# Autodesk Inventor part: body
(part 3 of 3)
sketch "Sketch150"
  geometry: L1 (-115, 140.221)-(-115, 134.332) reference; L2 (-115, 134.332)-(-122.377, 134.332) reference; L3 (-122.377, 134.332)-(-122.377, 140.221) reference; L4 (-122.377, 140.221)-(-115, 140.221) reference; L5 (-131, 141.166)-(-131, 148) reference; L6 (-131, 148)-(-123.589, 148) reference; L7 (-123.589, 148)-(-123.589, 141.166) reference; L8 (-123.589, 141.166)-(-131, 141.166) reference; L9 (-115, 141.166)-(-122.377, 141.166) reference; L10 (-122.377, 141.166)-(-122.377, 148) reference; L11 (-122.377, 148)-(-115, 148) reference; L12 (-115, 148)-(-115, 141.166) reference; L13 (-131, 140.221)-(-123.589, 140.221) reference; L14 (-123.589, 140.221)-(-123.589, 134.332) reference; L15 (-123.589, 134.332)-(-131, 134.332) reference; L16 (-131, 134.332)-(-131, 140.221) reference; L17 (-113.739, 149.568)-(-132.264, 149.568); L18 (-132.264, 149.568)-(-132.264, 132.978); L19 (-132.264, 132.978)-(-113.739, 132.978); L20 (-113.739, 132.978)-(-113.739, 149.568); 1 further point
  constraints: 8 end point, 2 parallel, 1 horizontal, 1 perpendicular
extrude "Extrusion150" cut sketch "Sketch150" distance "d349" = 1.25; taper "d350" = 0 deg
sketch "Sketch151"
  geometry: L1 (126.488, 149.508)-(126.488, 118) reference; L2 (126.488, 118)-(100, 118) reference; L3 (100, 118)-(100, 149.508) reference; L4 (100, 149.508)-(126.488, 149.508) reference; L5 (125.254, 134.332)-(101.544, 134.332); L6 (101.544, 134.332)-(101.544, 148.025); L7 (101.544, 148.025)-(125.254, 148.025); L8 (125.254, 148.025)-(125.254, 134.332); L9 (125.254, 132.001)-(101.544, 132.001); L10 (101.544, 132.001)-(101.544, 118.95); L11 (101.544, 118.95)-(125.254, 118.95); L12 (125.254, 118.95)-(125.254, 132.001); 1 further point
  constraints: 16 end point, 4 parallel, 2 horizontal, 2 perpendicular
extrude "Extrusion151" join sketch "Sketch151" distance "d351" = 1.25; taper "d352" = 0 deg
sketch "Sketch152"
  geometry: L1 (-125.254, 134.332)-(-125.254, 148.025) reference; L2 (-125.254, 148.025)-(-101.544, 148.025) reference; L3 (-101.544, 148.025)-(-101.544, 134.332) reference; L4 (-101.544, 134.332)-(-125.254, 134.332) reference; L5 (-126.488, 118)-(-126.488, 149.508) reference; L6 (-100, 149.508)-(-100, 118) reference; L7 (-126.488, 149.508)-(-100, 149.508) reference; L8 (-126.488, 132.993)-(-100, 132.993); 1 further point
  constraints: 2 end point, 2 point on line, 1 parallel
extrude "Extrusion152" join sketch "Sketch152" distance "d353" = 1.25; taper "d354" = 0 deg
sketch "Sketch153"
  geometry: L1 (101.544, 118.95)-(101.544, 132.001) reference; L2 (125.254, 132.001)-(125.254, 118.95) reference; L3 (125.254, 118.95)-(101.544, 118.95) reference; L4 (125.254, 148.025)-(125.254, 134.332) reference; L5 (101.544, 134.332)-(101.544, 148.025) reference; L6 (101.544, 148.025)-(125.254, 148.025) reference; L7 (125.254, 141.178)-(101.544, 141.178); L8 (101.544, 141.178)-(101.544, 140.119); L9 (101.544, 140.119)-(125.254, 140.119); L10 (125.254, 140.119)-(125.254, 141.178); L11 (125.254, 126.04)-(101.544, 126.04); L12 (101.544, 126.04)-(101.544, 124.925); L13 (101.544, 124.925)-(125.254, 124.925); L14 (125.254, 124.925)-(125.254, 126.04); L15 (108.73, 148.025)-(109.845, 148.025); L16 (109.845, 148.025)-(109.845, 118.95); L17 (109.845, 118.95)-(108.73, 118.95); L18 (108.73, 118.95)-(108.73, 148.025); L19 (117.478, 148.025)-(118.766, 148.025); L20 (118.766, 148.025)-(118.766, 118.95); L21 (118.766, 118.95)-(117.478, 118.95); L22 (117.478, 118.95)-(117.478, 148.025); 1 further point
  constraints: 32 end point, 8 parallel, 7 point on line, 4 horizontal, 4 perpendicular, 1 midpoint
extrude "Extrusion153" join sketch "Sketch153" distance "d355" = 0.75; taper "d356" = 0 deg
sketch "Sketch154"
  geometry: L1 (-117.478, 134.332)-(-118.766, 134.332) reference; L2 (-117.478, 134.332)-(-117.478, 140.119) reference; L3 (-117.478, 140.119)-(-109.845, 140.119) reference; L4 (-109.845, 140.119)-(-109.845, 134.332) reference; L5 (-108.73, 134.332)-(-109.845, 134.332) reference; L6 (-108.73, 134.332)-(-108.73, 140.119) reference; L7 (-108.73, 140.119)-(-101.544, 140.119) reference; L8 (-101.544, 141.178)-(-101.544, 140.119) reference; L9 (-101.544, 141.178)-(-108.73, 141.178) reference; L10 (-108.73, 141.178)-(-108.73, 148.025) reference; L11 (-109.845, 148.025)-(-108.73, 148.025) reference; L12 (-109.845, 148.025)-(-109.845, 141.178) reference; L13 (-109.845, 141.178)-(-117.478, 141.178) reference; L14 (-117.478, 141.178)-(-117.478, 148.025) reference; L15 (-118.766, 148.025)-(-117.478, 148.025) reference; L16 (-118.766, 148.025)-(-118.766, 141.178) reference; L17 (-118.766, 141.178)-(-125.254, 141.178) reference; L18 (-125.254, 140.119)-(-125.254, 141.178) reference; L19 (-125.254, 140.119)-(-118.766, 140.119) reference; L20 (-118.766, 140.119)-(-118.766, 134.332) reference; 1 further point
extrude "Extrusion154" join sketch "Sketch154" distance "d357" = 0.75; taper "d358" = 0 deg
sketch "Sketch155"
  geometry: L1 (117.478, 134.332)-(109.845, 134.332) reference; L2 (109.845, 134.332)-(109.845, 140.119) reference; L3 (109.845, 140.119)-(117.478, 140.119) reference; L4 (117.478, 140.119)-(117.478, 134.332) reference; L5 (108.73, 134.332)-(101.544, 134.332) reference; L6 (101.544, 134.332)-(101.544, 140.119) reference; L7 (101.544, 140.119)-(108.73, 140.119) reference; L8 (108.73, 140.119)-(108.73, 134.332) reference; L9 (118.766, 134.332)-(118.766, 140.119) reference; L10 (118.766, 140.119)-(125.254, 140.119) reference; L11 (125.254, 140.119)-(125.254, 134.332) reference; L12 (125.254, 134.332)-(118.766, 134.332) reference; L13 (101.544, 141.178)-(101.544, 148.025) reference; L14 (101.544, 148.025)-(108.73, 148.025) reference; L15 (108.73, 148.025)-(108.73, 141.178) reference; L16 (108.73, 141.178)-(101.544, 141.178) reference; L17 (109.845, 148.025)-(117.478, 148.025) reference; L18 (117.478, 148.025)-(117.478, 141.178) reference; L19 (117.478, 141.178)-(109.845, 141.178) reference; L20 (109.845, 141.178)-(109.845, 148.025) reference; L21 (125.254, 141.178)-(118.766, 141.178) reference; L22 (118.766, 141.178)-(118.766, 148.025) reference; L23 (118.766, 148.025)-(125.254, 148.025) reference; L24 (125.254, 148.025)-(125.254, 141.178) reference; L25 (99.825, 132.904)-(126.573, 132.904); L26 (126.573, 132.904)-(126.573, 149.564); L27 (126.573, 149.564)-(99.825, 149.564); L28 (99.825, 149.564)-(99.825, 132.904); 1 further point
  constraints: 8 end point, 2 parallel, 1 horizontal, 1 perpendicular
extrude "Extrusion155" cut sketch "Sketch155" distance "d359" = 0.75; taper "d360" = 0 deg
sketch "Sketch156"
  geometry: L1 (-132.114, -65.343)-(-128.305, -65.343); L2 (-128.305, -65.343)-(-128.305, -73.595); L3 (-128.305, -73.595)-(-132.114, -73.595); L4 (-132.114, -73.595)-(-132.114, -65.343); 1 further point
  constraints: 8 end point, 2 parallel, 1 horizontal, 1 perpendicular
extrude "Extrusion156" join sketch "Sketch156" distance "d361" = 6; taper "d363" = 0 deg; dims "d362" = 135.125, "d364" = 0
chamfer "Chamfer10" distance "d365" = 2; stored, may be unused: second distance "d366" = 2, angle "d367" = 45 deg
chamfer "Chamfer11" distance "d368" = 2.99; stored, may be unused: second distance "d369" = 2, angle "d370" = 45 deg
chamfer "Chamfer12" distance "d371" = 6.6; stored, may be unused: second distance "d372" = 2, angle "d373" = 45 deg
chamfer "Chamfer13" distance "d374" = 6.49; stored, may be unused: second distance "d375" = 2, angle "d376" = 45 deg
chamfer "Chamfer14" distance "d377" = 6.49; stored, may be unused: second distance "d378" = 2, angle "d379" = 45 deg
sketch "Sketch157"
  geometry: L1 (86, -22.522)-(104, -22.522) reference; L2 (104, -55)-(86, -55) reference; L3 (26, -55)-(8, -55) reference; L4 (8, -22.522)-(26, -22.522) reference; L5 (26, -22.522)-(26, -55) reference; L6 (17, -22.522)-(16, -22.522); L7 (16, -22.522)-(16, -55); L8 (16, -55)-(17, -55); L9 (17, -55)-(17, -22.522); L10 (17, -55)-(18, -55); L11 (18, -55)-(18, -22.522); L12 (18, -22.522)-(17, -22.522); L13 (17, -22.522)-(17, -55); L14 (95, -22.522)-(94, -22.522); L15 (94, -22.522)-(94, -55); L16 (94, -55)-(95, -55); L17 (95, -55)-(95, -22.522); L18 (95, -55)-(96, -55); L19 (96, -55)-(96, -22.522); L20 (96, -22.522)-(95, -22.522); L21 (95, -22.522)-(95, -55); L22 (104.519, -39.261)-(85.481, -39.261); L23 (85.481, -39.261)-(85.481, -38.261); L24 (85.481, -38.261)-(104.519, -38.261); L25 (104.519, -38.261)-(104.519, -39.261); L26 (104.519, -39.261)-(85.481, -38.261); L27 (85.481, -39.261)-(104.519, -38.261); L28 (8, -39.761)-(26, -39.761); L29 (26, -39.761)-(26, -38.761); L30 (26, -38.761)-(8, -38.761); L31 (8, -38.761)-(8, -39.761); L32 (8, -39.761)-(26, -38.761); L33 (26, -39.761)-(8, -38.761); 3 further points
  constraints: 56 end point, 12 parallel, 8 midpoint, 6 horizontal, 6 perpendicular, 5 point on line
  dimensions: "d380" = 1 distance of L8.end L7.end; "d381" = 1 distance of L12.end L11.end; "d382" = 1 distance of L16.end L15.end; "d383" = 1 distance of L20.end L19.end; "d384" = 1 distance of L22.end L23.end
extrude "Extrusion157" join sketch "Sketch157" distance "d385" = 2; taper "d386" = 0 deg
sketch "Sketch158"
  geometry: L1 (104.795, -31.141)-(85.205, -31.141); L2 (85.205, -31.141)-(85.205, -30.141); L3 (85.205, -30.141)-(104.795, -30.141); L4 (104.795, -30.141)-(104.795, -31.141); L5 (104.795, -31.141)-(85.205, -30.141); L6 (85.205, -31.141)-(104.795, -30.141); L7 (105.662, -47.88)-(84.338, -47.88); L8 (84.338, -47.88)-(84.338, -46.88); L9 (84.338, -46.88)-(105.662, -46.88); L10 (105.662, -46.88)-(105.662, -47.88); L11 (105.662, -47.88)-(84.338, -46.88); L12 (84.338, -47.88)-(105.662, -46.88); L13 (6.154, -30.141)-(27.846, -30.141); L14 (27.846, -30.141)-(27.846, -31.141); L15 (27.846, -31.141)-(6.154, -31.141); L16 (6.154, -31.141)-(6.154, -30.141); L17 (6.154, -30.141)-(27.846, -31.141); L18 (27.846, -30.141)-(6.154, -31.141); L19 (6.926, -46.88)-(27.074, -46.88); L20 (27.074, -46.88)-(27.074, -47.88); L21 (27.074, -47.88)-(6.926, -47.88); L22 (6.926, -47.88)-(6.926, -46.88); L23 (6.926, -46.88)-(27.074, -47.88); L24 (27.074, -46.88)-(6.926, -47.88); 5 further points
  constraints: 48 end point, 8 midpoint, 8 parallel, 4 horizontal, 4 perpendicular
  dimensions: "d387" = 1 distance of L1.end L2.end; "d388" = 1 distance of L7.end L8.end
extrude "Extrusion158" join sketch "Sketch158" distance "d389" = 2; taper "d390" = 0 deg
sketch "Sketch159"
  geometry: L1 (14, -178)-(126, -178) reference; L2 (31.976, -34.46)-(20.875, -34.46) reference; L3 (120.832, -178)-(115.933, -182.888); L4 (115.933, -182.888)-(24.079, -182.888); L5 (24.079, -182.888)-(19.202, -178); 1 further point
  constraints: 6 end point, 2 point on line, 1 parallel, 1 perpendicular
extrude "Extrusion159" join sketch "Sketch159" distance "d391" = 4.00022; taper "d392" = 0 deg
sketch "Sketch160"
  geometry: L1 (78, -15)-(34, -15); L2 (34, -15)-(34, -124); L3 (34, -124)-(78, -124); L4 (78, -124)-(78, -15); 1 further point
  constraints: 8 end point, 2 parallel, 1 horizontal, 1 perpendicular
extrude "Extrusion160" join sketch "Sketch160" distance "d393" = 4; taper "d394" = 0 deg
fillet "Fillet4" dims "d395" = 10
chamfer "Chamfer15" distance "d396" = 4; stored, may be unused: second distance "d397" = 2, angle "d398" = 45 deg
sketch "Sketch161"
  geometry: L1 (74, -47.663)-(74, -114) reference; L2 (56, -56)-(56, -32); L3 (53, -56)-(53, -32); L4 (59, -32)-(59, -56); L5 (56, -107)-(56, -83); L6 (53, -107)-(53, -83); L7 (59, -83)-(59, -107); C1 r 7 at (56, -107); C2 r 7 at (56, -56); A1 r 3 centre (56, -56) between (53, -56) and (59, -56); A2 r 3 centre (56, -32) between (59, -32) and (53, -32); A3 r 3 centre (56, -107) between (53, -107) and (59, -107); A4 r 3 centre (56, -83) between (59, -83) and (53, -83); 3 further points
  constraints: 16 end point, 8 point on circle, 8 tangent, 6 centre point, 4 parallel, 2 midpoint
extrude "Extrusion161" cut sketch "Sketch161" distance "d399" = 10.75; taper "d400" = 0 deg
sketch "Sketch162"
  geometry: L1 (53, -49.675)-(53, -32) reference; L2 (59, -32)-(59, -49.675) reference; L3 (53, -100.675)-(53, -83) reference; L4 (59, -83)-(59, -100.675) reference; L5 (38, -114)-(38, -47.663) reference; L6 (56, -107)-(56, -83); L7 (49, -107)-(49, -83); L8 (63, -83)-(63, -107); L9 (56, -56)-(56, -32); L10 (49, -56)-(49, -32); L11 (63, -32)-(63, -56); A1 r 3 centre (56, -32) between (59, -32) and (53, -32) reference; A2 r 7 centre (56, -56) between (53, -49.675) and (59, -49.675) reference; A3 r 3 centre (56, -83) between (59, -83) and (53, -83) reference; A4 r 7 centre (56, -107) between (53, -100.675) and (59, -100.675) reference; A5 r 7 centre (56, -107) between (49, -107) and (63, -107); A6 r 7 centre (56, -83) between (63, -83) and (49, -83); A7 r 7 centre (56, -56) between (49, -56) and (63, -56); A8 r 7 centre (56, -32) between (63, -32) and (49, -32); 3 further points
  constraints: 16 end point, 8 point on circle, 8 tangent, 4 centre point, 4 parallel, 2 midpoint
extrude "Extrusion162" cut sketch "Sketch162" distance "d401" = 4; taper "d402" = 0 deg
chamfer "Chamfer16" distance "d403" = 3; stored, may be unused: second distance "d404" = 2, angle "d405" = 45 deg
fillet "Fillet5" dims "d406" = 6
sketch "Sketch163"
  geometry: L1 (0, 0)-(0, 86) reference; L2 (112, 0)-(0, 0); L3 (0, 0)-(0, 5); L4 (0, 5)-(112, 5); L5 (112, 5)-(112, 0); 1 further point
  constraints: 8 end point, 2 parallel, 1 horizontal, 1 perpendicular, 1 point on line
extrude "Extrusion163" join sketch "Sketch163" distance "d407" = 6; taper "d408" = 0 deg
chamfer "Chamfer17" distance "d409" = 6; stored, may be unused: second distance "d410" = 2, angle "d411" = 45 deg
sketch "Sketch164"
  geometry: L1 (112, -66.522)-(107, -66.522); L2 (107, -66.522)-(107, -62); L3 (107, -62)-(112, -62); L4 (112, -62)-(112, -66.522); L5 (0, -66.522)-(5, -66.522); L6 (5, -66.522)-(5, -62); L7 (5, -62)-(0, -62); L8 (0, -62)-(0, -66.522); 1 further point
  constraints: 16 end point, 4 parallel, 2 horizontal, 2 perpendicular
extrude "Extrusion164" join sketch "Sketch164" distance "d412" = 87; taper "d413" = 0 deg
chamfer "Chamfer18" distance "d414" = 5; stored, may be unused: second distance "d415" = 2, angle "d416" = 45 deg
sketch "Sketch165"
  geometry: L1 (14, -200)-(14, -178) reference; L2 (115.933, -182.888)-(120.832, -178) reference; L3 (126, -178)-(126, -200) reference; L4 (31.976, -34.46)-(20.875, -34.46) reference; L5 (14, -196.844)-(18.833, -196.844); L6 (18.833, -196.844)-(18.833, -186.125); L7 (18.833, -186.125)-(14, -181.281); L8 (126, -196.844)-(121.146, -196.844); L9 (121.146, -196.844)-(121.146, -186.125); L10 (121.146, -186.125)-(126, -181.282); 1 further point
  constraints: 12 end point, 5 perpendicular, 4 point on line, 1 parallel
extrude "Extrusion165" join sketch "Sketch165" distance "d417" = 90.22222; taper "d418" = 0 deg
chamfer "Chamfer19" distance "d419" = 4.75; stored, may be unused: second distance "d420" = 2, angle "d421" = 45 deg
chamfer "Chamfer20" distance "d422" = 1; stored, may be unused: second distance "d423" = 2, angle "d424" = 45 deg
chamfer "Chamfer21" distance "d425" = 0.5; stored, may be unused: second distance "d426" = 2, angle "d427" = 45 deg
chamfer "Chamfer22" distance "d428" = 0.5; stored, may be unused: second distance "d429" = 2, angle "d430" = 45 deg
chamfer "Chamfer23" distance "d431" = 0.5; stored, may be unused: second distance "d432" = 2, angle "d433" = 45 deg
chamfer "Chamfer24" distance "d434" = 0.5; stored, may be unused: second distance "d435" = 2, angle "d436" = 45 deg
chamfer "Chamfer25" distance "d437" = 0.5; stored, may be unused: second distance "d438" = 2, angle "d439" = 45 deg
chamfer "Chamfer26" distance "d440" = 0.5; stored, may be unused: second distance "d441" = 2, angle "d442" = 45 deg
chamfer "Chamfer27" distance "d443" = 2; stored, may be unused: second distance "d444" = 0.5, angle "d445" = 45 deg
chamfer "Chamfer28" distance "d446" = 2; stored, may be unused: second distance "d447" = 0.5, angle "d448" = 45 deg
chamfer "Chamfer29" distance "d449" = 2; stored, may be unused: second distance "d450" = 0.5, angle "d451" = 45 deg
chamfer "Chamfer30" distance "d452" = 2; stored, may be unused: second distance "d453" = 0.5, angle "d454" = 45 deg
chamfer "Chamfer31" distance "d455" = 1.5; stored, may be unused: second distance "d456" = 0.5, angle "d457" = 45 deg
chamfer "Chamfer32" distance "d458" = 2; stored, may be unused: second distance "d459" = 0.5, angle "d460" = 45 deg
chamfer "Chamfer33" distance "d461" = 2; stored, may be unused: second distance "d462" = 0.5, angle "d463" = 45 deg
chamfer "Chamfer34" distance "d464" = 2; stored, may be unused: second distance "d465" = 0.5, angle "d466" = 45 deg
chamfer "Chamfer35" distance "d467" = 2; stored, may be unused: second distance "d468" = 0.5, angle "d469" = 45 deg
chamfer "Chamfer36" distance "d470" = 2; stored, may be unused: second distance "d471" = 0.5, angle "d472" = 45 deg
chamfer "Chamfer37" distance "d473" = 2; stored, may be unused: second distance "d474" = 0.5, angle "d475" = 45 deg
chamfer "Chamfer38" distance "d476" = 2; stored, may be unused: second distance "d477" = 0.5, angle "d478" = 45 deg
chamfer "Chamfer39" distance "d479" = 2; stored, may be unused: second distance "d480" = 0.5, angle "d481" = 45 deg
chamfer "Chamfer40" distance "d482" = 2; stored, may be unused: second distance "d483" = 0.5, angle "d484" = 45 deg
chamfer "Chamfer41" distance "d485" = 2; stored, may be unused: second distance "d486" = 0.5, angle "d487" = 45 deg
chamfer "Chamfer42" distance "d488" = 2; stored, may be unused: second distance "d489" = 0.5, angle "d490" = 45 deg
chamfer "Chamfer43" distance "d491" = 2; stored, may be unused: second distance "d492" = 0.5, angle "d493" = 45 deg
chamfer "Chamfer44" distance "d494" = 1.75; stored, may be unused: second distance "d495" = 0.5, angle "d496" = 45 deg
chamfer "Chamfer45" distance "d497" = 2; stored, may be unused: second distance "d498" = 0.5, angle "d499" = 45 deg
chamfer "Chamfer46" distance "d500" = 2; stored, may be unused: second distance "d501" = 0.5, angle "d502" = 45 deg
chamfer "Chamfer47" distance "d503" = 2; stored, may be unused: second distance "d504" = 0.5, angle "d505" = 45 deg
chamfer "Chamfer48" distance "d506" = 2; stored, may be unused: second distance "d507" = 0.5, angle "d508" = 45 deg
chamfer "Chamfer49" distance "d509" = 2; stored, may be unused: second distance "d510" = 0.5, angle "d511" = 45 deg
chamfer "Chamfer50" distance "d512" = 2; stored, may be unused: second distance "d513" = 0.5, angle "d514" = 45 deg
chamfer "Chamfer51" distance "d515" = 2; stored, may be unused: second distance "d516" = 0.5, angle "d517" = 45 deg
chamfer "Chamfer52" distance "d518" = 2; stored, may be unused: second distance "d519" = 0.5, angle "d520" = 45 deg
chamfer "Chamfer53" distance "d521" = 2; stored, may be unused: second distance "d522" = 0.5, angle "d523" = 45 deg
chamfer "Chamfer54" distance "d524" = 2; stored, may be unused: second distance "d525" = 0.5, angle "d526" = 45 deg
chamfer "Chamfer55" distance "d527" = 2; stored, may be unused: second distance "d528" = 0.5, angle "d529" = 45 deg
chamfer "Chamfer56" distance "d530" = 2; stored, may be unused: second distance "d531" = 0.5, angle "d532" = 45 deg
chamfer "Chamfer57" distance "d533" = 2; stored, may be unused: second distance "d534" = 0.5, angle "d535" = 45 deg
chamfer "Chamfer58" distance "d536" = 2; stored, may be unused: second distance "d537" = 0.5, angle "d538" = 45 deg
chamfer "Chamfer59" distance "d539" = 2; stored, may be unused: second distance "d540" = 0.5, angle "d541" = 45 deg
chamfer "Chamfer60" distance "d542" = 2; stored, may be unused: second distance "d543" = 0.5, angle "d544" = 45 deg
chamfer "Chamfer61" distance "d545" = 2; stored, may be unused: second distance "d546" = 0.5, angle "d547" = 45 deg
chamfer "Chamfer62" distance "d548" = 2; stored, may be unused: second distance "d549" = 0.5, angle "d550" = 45 deg
chamfer "Chamfer63" distance "d551" = 2; stored, may be unused: second distance "d552" = 0.5, angle "d553" = 45 deg
chamfer "Chamfer64" distance "d554" = 2; stored, may be unused: second distance "d555" = 0.5, angle "d556" = 45 deg
chamfer "Chamfer65" distance "d557" = 2; stored, may be unused: second distance "d558" = 0.5, angle "d559" = 45 deg
chamfer "Chamfer66" distance "d560" = 2; stored, may be unused: second distance "d561" = 0.5, angle "d562" = 45 deg
chamfer "Chamfer67" distance "d563" = 2; stored, may be unused: second distance "d564" = 0.5, angle "d565" = 45 deg
chamfer "Chamfer68" distance "d566" = 2; stored, may be unused: second distance "d567" = 0.5, angle "d568" = 45 deg
chamfer "Chamfer69" distance "d569" = 2; stored, may be unused: second distance "d570" = 0.5, angle "d571" = 45 deg
chamfer "Chamfer70" distance "d572" = 2; stored, may be unused: second distance "d573" = 0.5, angle "d574" = 45 deg
chamfer "Chamfer71" distance "d575" = 2; stored, may be unused: second distance "d576" = 0.5, angle "d577" = 45 deg
chamfer "Chamfer72" distance "d578" = 2; stored, may be unused: second distance "d579" = 0.5, angle "d580" = 45 deg
chamfer "Chamfer73" distance "d581" = 2; stored, may be unused: second distance "d582" = 0.5, angle "d583" = 45 deg
chamfer "Chamfer74" distance "d584" = 2; stored, may be unused: second distance "d585" = 0.5, angle "d586" = 45 deg
chamfer "Chamfer75" distance "d587" = 2; stored, may be unused: second distance "d588" = 0.5, angle "d589" = 45 deg
chamfer "Chamfer76" distance "d590" = 2; stored, may be unused: second distance "d591" = 0.5, angle "d592" = 45 deg
chamfer "Chamfer77" distance "d593" = 2; stored, may be unused: second distance "d594" = 0.5, angle "d595" = 45 deg
chamfer "Chamfer78" distance "d596" = 2; stored, may be unused: second distance "d597" = 0.5, angle "d598" = 45 deg
chamfer "Chamfer79" distance "d599" = 2; stored, may be unused: second distance "d600" = 0.5, angle "d601" = 45 deg
chamfer "Chamfer80" distance "d602" = 1.25; stored, may be unused: second distance "d603" = 0.5, angle "d604" = 45 deg
chamfer "Chamfer81" distance "d605" = 1.25; stored, may be unused: second distance "d606" = 0.5, angle "d607" = 45 deg
chamfer "Chamfer82" distance "d608" = 1.25; stored, may be unused: second distance "d609" = 0.5, angle "d610" = 45 deg
chamfer "Chamfer83" distance "d611" = 2; stored, may be unused: second distance "d612" = 0.5, angle "d613" = 45 deg
chamfer "Chamfer84" distance "d614" = 2; stored, may be unused: second distance "d615" = 0.5, angle "d616" = 45 deg
chamfer "Chamfer85" distance "d617" = 2; stored, may be unused: second distance "d618" = 0.5, angle "d619" = 45 deg
chamfer "Chamfer86" distance "d620" = 2; stored, may be unused: second distance "d621" = 0.5, angle "d622" = 45 deg
chamfer "Chamfer87" distance "d623" = 2; stored, may be unused: second distance "d624" = 0.5, angle "d625" = 45 deg
chamfer "Chamfer88" distance "d626" = 2; stored, may be unused: second distance "d627" = 0.5, angle "d628" = 45 deg
chamfer "Chamfer89" distance "d629" = 2; stored, may be unused: second distance "d630" = 0.5, angle "d631" = 45 deg
chamfer "Chamfer90" distance "d632" = 2; stored, may be unused: second distance "d633" = 0.5, angle "d634" = 45 deg
chamfer "Chamfer91" distance "d635" = 2; stored, may be unused: second distance "d636" = 0.5, angle "d637" = 45 deg
chamfer "Chamfer92" distance "d638" = 2; stored, may be unused: second distance "d639" = 0.5, angle "d640" = 45 deg
chamfer "Chamfer93" distance "d641" = 2; stored, may be unused: second distance "d642" = 0.5, angle "d643" = 45 deg
chamfer "Chamfer94" distance "d644" = 2; stored, may be unused: second distance "d645" = 0.5, angle "d646" = 45 deg
chamfer "Chamfer95" distance "d647" = 0.5; stored, may be unused: second distance "d648" = 0.5, angle "d649" = 45 deg
sketch "Sketch166"
  geometry: L1 (-9.13, -36.87)-(0.44, -36.87); L2 (0.44, -36.87)-(0.44, -53.44); L3 (0.44, -53.44)-(-9.13, -53.44); L4 (-9.13, -53.44)-(-9.13, -36.87); 1 further point
  constraints: 8 end point, 2 parallel, 1 horizontal, 1 perpendicular
extrude "Extrusion166" cut sketch "Sketch166" distance "d650" = 18.77778; taper "d651" = 0 deg
chamfer "Chamfer96" distance "d652" = 3.5; stored, may be unused: second distance "d653" = 0.5, angle "d654" = 45 deg
chamfer "Chamfer97" distance "d655" = 2; stored, may be unused: second distance "d656" = 0.5, angle "d657" = 45 deg
sketch "Sketch167"
  geometry: L1 (4, -55)-(4, -35) reference; L2 (2, -33)-(-11, -33) reference; L3 (-13, -35)-(-13, -55) reference; L4 (-4.5, -33)-(-6, -33); L5 (-6, -33)-(-6, -35); L6 (-6, -35)-(-4.5, -35); L7 (-4.5, -35)-(-4.5, -33); L8 (-4.5, -35)-(-3, -35); L9 (-3, -35)-(-3, -33); L10 (-3, -33)-(-4.5, -33); L11 (-4.5, -33)-(-4.5, -35); L12 (4, -45)-(2.5, -45); L13 (2.5, -45)-(2.5, -43); L14 (2.5, -43)-(4, -43); L15 (4, -43)-(4, -45); L16 (4, -45)-(2.5, -45); L17 (2.5, -45)-(2.5, -47); L18 (2.5, -47)-(4, -47); L19 (4, -47)-(4, -45); L20 (-13, -43)-(-11.5, -43); L21 (-11.5, -43)-(-11.5, -47); L22 (-11.5, -47)-(-13, -47); L23 (-13, -47)-(-13, -43); 1 further point
  constraints: 40 end point, 10 parallel, 5 horizontal, 5 perpendicular, 2 midpoint, 2 point on line
  dimensions: "d658" = 1.5 distance of L13.end L14.end; "d659" = 1.5 distance of L21.end L22.end
extrude "Extrusion167" join sketch "Sketch167" distance "d660" = 13.02778; taper "d661" = 0 deg
chamfer "Chamfer98" distance "d662" = 1.5; stored, may be unused: second distance "d663" = 0.5, angle "d664" = 45 deg
chamfer "Chamfer99" distance "d665" = 1.5; stored, may be unused: second distance "d666" = 0.5, angle "d667" = 45 deg
sketch "Sketch168"
  geometry: L1 (-1.712, 154.276)-(2.594, 154.276); L2 (2.594, 154.276)-(2.594, 150.276); L3 (2.594, 150.276)-(-4.582, 150.276); L4 (2.594, 149)-(2.594, 145); L5 (2.594, 145)-(-6.406, 145); L6 (-6.406, 145)-(-6.406, 147.734); L7 (-5.497, 149)-(2.594, 149); L8 (-7.671, 145.97)-(-7.671, 145); L9 (-7.671, 145)-(-8.367, 145); L10 (6, 144)-(6, 140); L11 (6, 140)-(-3, 140); L12 (-3, 140)-(-3, 144); L13 (-3, 144)-(6, 144); L14 (-4, 144)-(-4, 140); L15 (-4, 140)-(-11.954, 140); L16 (-9.084, 144)-(-4, 144); L17 (1, 139)-(1, 135); L18 (1, 135)-(-8, 135); L19 (-8, 135)-(-8, 139); L20 (-8, 139)-(1, 139); L21 (-9, 139)-(-9, 135); L22 (-9, 135)-(-15.541, 135); L23 (-12.671, 139)-(-9, 139); L24 (6, 134)-(6, 130); L25 (6, 130)-(-3, 130); L26 (-3, 130)-(-3, 134); L27 (-3, 134)-(6, 134); L28 (-4, 134)-(-4, 130); L29 (-4, 130)-(-13, 130); L30 (-13, 130)-(-13, 134); L31 (-13, 134)-(-4, 134); L32 (-14, 134)-(-14, 130); L33 (-14, 130)-(-19.128, 130); L34 (-16.258, 134)-(-14, 134); L35 (-9, 129)-(-9, 125); L36 (-9, 125)-(-18, 125); L37 (-18, 125)-(-18, 129); L38 (-18, 129)-(-9, 129); L39 (1, 129)-(1, 125); L40 (1, 125)-(-8, 125); L41 (-8, 125)-(-8, 129); L42 (-8, 129)-(1, 129); L43 (-19, 129)-(-19, 125); L44 (-19, 125)-(-22, 125); L45 (-19.845, 129)-(-19, 129); L46 (-3, 124)-(6, 124); L47 (6, 120)-(-3, 120); L48 (6, 124)-(6, 120); L49 (-4, 124)-(-4, 120); L50 (-8, 119)-(1, 119); L51 (1, 119)-(1, 115); L52 (1, 115)-(-8, 115); L53 (-8, 115)-(-8, 119); L54 (-3, 120)-(-3, 124); L55 (-13, 124)-(-4, 124); L56 (-4, 120)-(-13, 120); L57 (-13, 120)-(-13, 124); L58 (-18, 119)-(-9, 119); L59 (-9, 115)-(-18, 115); L60 (-9, 119)-(-9, 115); L61 (-18, 115)-(-18, 119); L62 (-19, 119)-(-19, 115); L63 (-14, 120)-(-23, 120); L64 (-23, 120)-(-23, 124)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; 1 further point
  constraints: 716 end point, 172 parallel, 88 horizontal, 88 perpendicular, 2 collinear, 2 point on line
extrude "Extrusion168" cut sketch "Sketch168" distance "d668" = 0.5; taper "d669" = 0 deg
sketch "Sketch169"
  geometry: L1 (0.5, 157)-(0.5, 144) reference; L2 (0.242, 157)-(0.5, 157) reference; L3 (-22, 124)-(-22, 125.957) reference; L4 (0.5, 14)-(-3, 14) reference; L5 (-9.072, 144)-(-4, 144); L6 (-4, 144)-(-4, 140); L7 (-4, 140)-(-11.938, 140); L8 (-9.072, 139)-(-9.072, 135); L9 (-9.072, 135)-(-15.521, 135); L10 (-9.072, 139)-(-12.655, 139); L11 (-14, 134)-(-14, 130); L12 (-14, 130)-(-19.103, 130); L13 (-14, 134)-(-16.237, 134); L14 (-19.82, 129)-(-19.103, 129); L15 (-19.103, 129)-(-19.103, 124.978); L16 (-19.103, 124.978)-(-22, 124.978); L17 (0.5, 145)-(-8.356, 145); L18 (0.5, 149.41)-(-5.196, 149.41); L19 (0.5, 150.5)-(-4.415, 150.5); 1 further point
  constraints: 30 end point, 8 parallel, 6 perpendicular, 2 midpoint, 2 point on line, 11 other
extrude "Extrusion169" join sketch "Sketch169" distance "d670" = 0.5; taper "d671" = 0 deg
sketch "Sketch170"
  geometry: L1 (-1.322, 151.905)-(-1.322, 144.25) reference; L2 (0, 151.905)-(0, 176.929) reference; L3 (-5.936, 162.782)-(-5.936, 173.075) reference; L4 (-6.364, 162)-(-6.364, 155.5) reference; L5 (-7.071, 9)-(0, 9); L6 (0, 9)-(0, 10); L7 (0, 10)-(-7.071, 10); L8 (-7.071, 10)-(-7.071, 9); L9 (-7.071, 14)-(0, 14); L10 (0, 14)-(0, 15); L11 (0, 15)-(-7.071, 15); L12 (-7.071, 15)-(-7.071, 14); L13 (-7.071, 19)-(0, 19); L14 (0, 19)-(0, 20); L15 (0, 20)-(-7.071, 20); L16 (-7.071, 20)-(-7.071, 19); L17 (-7.071, 24)-(0, 24); L18 (0, 24)-(0, 25); L19 (0, 25)-(-7.071, 25); L20 (-7.071, 25)-(-7.071, 24); L21 (-7.071, 29)-(0, 29); L22 (0, 29)-(0, 30); L23 (0, 30)-(-7.071, 30); L24 (-7.071, 30)-(-7.071, 29); L25 (-7.071, 34)-(0, 34); L26 (0, 34)-(0, 35); L27 (0, 35)-(-7.071, 35); L28 (-7.071, 35)-(-7.071, 34); L29 (-7.071, 39)-(0, 39); L30 (0, 39)-(0, 40); L31 (0, 40)-(-7.071, 40); L32 (-7.071, 40)-(-7.071, 39); L33 (-7.071, 44)-(0, 44); L34 (0, 44)-(0, 45); L35 (0, 45)-(-7.071, 45); L36 (-7.071, 45)-(-7.071, 44); L37 (-7.071, 49)-(0, 49); L38 (0, 49)-(0, 50); L39 (0, 50)-(-7.071, 50); L40 (-7.071, 50)-(-7.071, 49); L41 (-7.071, 54)-(0, 54); L42 (0, 54)-(0, 55); L43 (0, 55)-(-7.071, 55); L44 (-7.071, 55)-(-7.071, 54); L45 (-7.071, 59)-(0, 59); L46 (0, 59)-(0, 60); L47 (0, 60)-(-7.071, 60); L48 (-7.071, 60)-(-7.071, 59); L49 (-7.071, 64)-(0, 64); L50 (0, 64)-(0, 65); L51 (0, 65)-(-7.071, 65); L52 (-7.071, 65)-(-7.071, 64); L53 (-7.071, 69)-(0, 69); L54 (0, 69)-(0, 70); L55 (0, 70)-(-7.071, 70); L56 (-7.071, 70)-(-7.071, 69); L57 (-7.071, 74)-(0, 74); L58 (0, 74)-(0, 75); L59 (0, 75)-(-7.071, 75); L60 (-7.071, 75)-(-7.071, 74); L61 (-7.071, 79)-(0, 79); L62 (0, 79)-(0, 80); L63 (0, 80)-(-7.071, 80); L64 (-7.071, 80)-(-7.071, 79)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; 3 further points
  constraints: 264 end point, 66 parallel, 33 horizontal, 33 perpendicular, 9 point on line, 28 other
extrude "Extrusion170" cut sketch "Sketch170" distance "d672" = 0.5; taper "d673" = 0 deg
sketch "Sketch171"
  geometry: L1 (4.693, -136.789)-(4.693, -136.289) reference; L2 (4.693, -132.289)-(4.693, -131.289) reference; L3 (4.693, -127.289)-(4.693, -126.289) reference; L4 (4.693, -122.289)-(4.693, -121.289) reference; L5 (4.693, -117.289)-(4.693, -116.289) reference; L6 (4.693, -112.289)-(4.693, -111.289) reference; L7 (4.693, -107.289)-(4.693, -106.289) reference; L8 (4.693, -102.289)-(4.693, -101.289) reference; L9 (4.693, -97.289)-(4.693, -96.289) reference; L10 (4.693, -92.289)-(4.693, -91.289) reference; L11 (4.693, -87.289)-(4.693, -86.289) reference; L12 (4.693, -82.289)-(4.693, -81.289) reference; L13 (4.693, -77.289)-(4.693, -76.289) reference; L14 (4.693, -72.289)-(4.693, -71.289) reference; L15 (4.693, -67.289)-(4.693, -66.289) reference; L16 (4.693, -62.289)-(4.693, -61.289) reference; L17 (4.693, -57.289)-(4.693, -56.289) reference; L18 (4.693, -52.289)-(4.693, -51.289) reference; L19 (4.693, -47.289)-(4.693, -46.289) reference; L20 (4.693, -42.289)-(4.693, -41.289) reference; L21 (4.693, -37.289)-(4.693, -36.289) reference; L22 (4.693, -32.289)-(4.693, -31.289) reference; L23 (4.693, -27.289)-(4.693, -26.289) reference; L24 (4.693, -22.289)-(4.693, -21.289) reference; L25 (4.693, -17.289)-(4.693, -16.289) reference; L26 (4.693, -12.289)-(4.693, -11.311) reference; L27 (0.066, -12.024)-(-0.044, -11.149) reference; L28 (-0.372, -12.52)-(0.066, -12.024) reference; L29 (0.066, -20.024)-(-0.872, -12.52) reference; L30 (0.066, -28.024)-(-0.872, -20.52) reference; L31 (0.066, -36.024)-(-0.872, -28.52) reference; L32 (-0.372, -36.52)-(0.066, -36.024) reference; L33 (-0.872, -36.52)-(-0.372, -36.52) reference; L34 (0.066, -44.024)-(-0.872, -36.52) reference; L35 (0.066, -52.024)-(-0.872, -44.52) reference; L36 (-0.372, -52.52)-(0.066, -52.024) reference; L37 (0.066, -60.024)-(-0.872, -52.52) reference; L38 (0.066, -68.024)-(-0.872, -60.52) reference; L39 (0.066, -76.024)-(-0.872, -68.52) reference; L40 (-0.372, -76.52)-(0.066, -76.024) reference; L41 (-0.872, -76.52)-(-0.372, -76.52) reference; L42 (0.066, -84.024)-(-0.872, -76.52) reference; L43 (0.066, -92.024)-(-0.872, -84.52) reference; L44 (-0.372, -92.52)-(0.066, -92.024) reference; L45 (0.066, -100.024)-(-0.872, -92.52) reference; L46 (0.066, -108.024)-(-0.872, -100.52) reference; L47 (0.066, -116.024)-(-0.872, -108.52) reference; L48 (-0.372, -116.52)-(0.066, -116.024) reference; L49 (-0.872, -116.52)-(-0.372, -116.52) reference; L50 (0.066, -124.024)-(-0.872, -116.52) reference; L51 (0.066, -132.024)-(-0.872, -124.52) reference; L52 (-0.368, -132.583)-(0.066, -132.024) reference; L53 (0.128, -140.645)-(-0.872, -132.645) reference; L54 (-0.436, -141.289)-(0.128, -140.645) reference; L55 (0.193, -141.289)-(-0.436, -141.289) reference; L56 (4.693, -136.789)-(0.193, -141.289) reference; L57 (4.693, -11.311)-(-0.044, -11.149); L58 (4.693, -12.289)-(-0.153, -12.272); L59 (4.693, -16.289)-(-0.403, -16.272); L60 (4.693, -17.289)-(-0.278, -17.273); L61 (4.693, -21.289)-(-0.778, -21.271); L62 (4.693, -22.289)-(-0.653, -22.272); L63 (4.693, -26.289)-(-0.153, -26.273); L64 (4.693, -27.289)-(-0.028, -27.274)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; 1 further point
  constraints: 102 end point, 39 parallel, 39 point on line, 11 midpoint
extrude "Extrusion171" cut sketch "Sketch171" distance "d674" = 0.5; taper "d675" = 0 deg
sketch "Sketch172"
  geometry: L1 (78, -66.522)-(107, -66.522) reference; L2 (107, -66.522)-(107, -62) reference; L3 (34, -66.522)-(5, -66.522); L4 (5, -66.522)-(5, -62); L5 (5, -62)-(34, -62); L6 (34, -62)-(34, -66.522); L7 (78, -66.522)-(107, -66.522); L8 (107, -66.522)-(107, -62); L9 (107, -62)-(78, -62); L10 (78, -62)-(78, -66.522); 1 further point
  constraints: 16 end point, 4 parallel, 2 horizontal, 2 perpendicular
extrude "Extrusion172" join sketch "Sketch172" distance "d676" = 29; taper "d677" = 0 deg
chamfer "Chamfer100" distance "d678" = 29; stored, may be unused: second distance "d679" = 0.5, angle "d680" = 45 deg
sketch "Sketch173"
  geometry: L1 (112, 4.183)-(112, -57) reference; L2 (0, -57)-(0, 4.183) reference; L3 (34, -22.522)-(0, -22.522); L4 (0, -22.522)-(0, -19); L5 (0, -19)-(34, -19); L6 (34, -19)-(34, -22.522); L7 (78, -22.522)-(112, -22.522); L8 (112, -22.522)-(112, -19); L9 (112, -19)-(78, -19); L10 (78, -19)-(78, -22.522); 1 further point
  constraints: 16 end point, 4 parallel, 2 horizontal, 2 perpendicular, 2 point on line
extrude "Extrusion173" join sketch "Sketch173" distance "d681" = 34; taper "d682" = 0 deg
chamfer "Chamfer101" distance "d683" = 34; stored, may be unused: second distance "d684" = 0.5, angle "d685" = 45 deg
chamfer "Chamfer102" distance "d686" = 8; stored, may be unused: second distance "d687" = 0.5, angle "d688" = 45 deg
chamfer "Chamfer103" distance "d689" = 7; stored, may be unused: second distance "d690" = 0.5, angle "d691" = 45 deg
sketch "Sketch174"
  geometry: L1 (18, -20)-(16, -20); L2 (16, -20)-(16, -57.407); L3 (16, -57.407)-(18, -57.407); L4 (18, -57.407)-(18, -20); L5 (26, -20)-(28, -20); L6 (28, -20)-(28, -57.407); L7 (28, -57.407)-(26, -57.407); L8 (26, -57.407)-(26, -20); L9 (34, -57.407)-(32, -57.407); L10 (32, -57.407)-(32, -20); L11 (32, -20)-(34, -20); L12 (34, -20)-(34, -57.407); 1 further point
  constraints: 24 end point, 6 parallel, 3 horizontal, 3 perpendicular
extrude "Extrusion174" join sketch "Sketch174" distance "d692" = 1; taper "d693" = 0 deg
sketch "Sketch175"
  geometry: L1 (96, -20)-(94, -20); L2 (94, -20)-(94, -58); L3 (94, -58)-(96, -58); L4 (96, -58)-(96, -20); L5 (86, -20)-(84, -20); L6 (84, -20)-(84, -58); L7 (84, -58)-(86, -58); L8 (86, -58)-(86, -20); L9 (78, -20)-(80, -20); L10 (80, -20)-(80, -58); L11 (80, -58)-(78, -58); L12 (78, -58)-(78, -20); 1 further point
  constraints: 24 end point, 6 parallel, 3 horizontal, 3 perpendicular
extrude "Extrusion175" join sketch "Sketch175" distance "d694" = 1; taper "d695" = 0 deg
chamfer "Chamfer104" distance "d696" = 1; stored, may be unused: second distance "d697" = 0.5, angle "d698" = 45 deg
chamfer "Chamfer105" distance "d699" = 0.6; stored, may be unused: second distance "d700" = 0.5, angle "d701" = 45 deg
sketch "Sketch176"
  geometry: L1 (78, -19)-(112, -19) reference; L2 (29, -22.522)-(83, -22.522); L3 (83, -22.522)-(83, -19); L4 (83, -19)-(29, -19); L5 (29, -19)-(29, -22.522); 1 further point
  constraints: 8 end point, 2 parallel, 1 horizontal, 1 perpendicular, 1 point on line
extrude "Extrusion176" join sketch "Sketch176" distance "d702" = 2; taper "d703" = 0 deg
chamfer "Chamfer106" distance "d704" = 2; stored, may be unused: second distance "d705" = 0.5, angle "d706" = 45 deg
sketch "Sketch177"
  geometry: L1 (0, -19)-(112, -19) reference; L2 (0, 4.183)-(112, 4.183) reference; L3 (34, -19)-(32, -19); L4 (32, -19)-(32, 4.183); L5 (32, 4.183)-(34, 4.183); L6 (34, 4.183)-(34, -19); L7 (78, -19)-(80, -19); L8 (80, -19)-(80, 4.183); L9 (80, 4.183)-(78, 4.183); L10 (78, 4.183)-(78, -19); 1 further point
  constraints: 16 end point, 4 parallel, 3 point on line, 2 horizontal, 2 perpendicular
extrude "Extrusion177" join sketch "Sketch177" distance "d707" = 18; taper "d708" = 0 deg
sketch "Sketch178"
  geometry: L1 (0, 23.183)-(-18, 23.183) reference; L2 (0, 0)-(-2, 0) reference; L3 (-18, 23.183)-(-18, 42); L4 (-12.96, 42)-(0, 24); L5 (0, 24)-(0, 23.183); L6 (0, 24)-(0, 23.183); L7 (-2, 0)-(-18, 0) reference; L8 (-12.96, 42)-(-18, 42); 1 further point
  constraints: 10 end point, 2 parallel, 1 collinear, 1 perpendicular
extrude "Extrusion178" join sketch "Sketch178" distance "d709" = 2; taper "d710" = 0 deg
sketch "Sketch179"
  geometry: L1 (0, 23.183)-(18, 23.183) reference; L2 (18, 23.183)-(18, 41.728); L3 (18, 41.728)-(12, 41.728); L4 (12, 41.728)-(0, 24); L5 (0, 24)-(0, 23.183); 1 further point
  constraints: 8 end point, 2 perpendicular, 1 parallel
extrude "Extrusion179" join sketch "Sketch179" distance "d711" = 2; taper "d712" = 0 deg
sketch "Sketch180"
  geometry: L1 (32, -19)-(32, 19.478) reference; L2 (32, -19)-(34, -19) reference; L3 (34, -19)-(34, 19.478) reference; L4 (32, 19.478)-(34, 19.478) reference; 1 further point
extrude "Extrusion180" join sketch "Sketch180" distance "d713" = 6; taper "d714" = 0 deg
sketch "Sketch181"
  geometry: L1 (78, -19)-(80, -19) reference; L2 (80, -19)-(80, 19.478) reference; L3 (78, 19.478)-(80, 19.478) reference; L4 (78, -19)-(78, 19.478) reference; 1 further point
extrude "Extrusion181" join sketch "Sketch181" distance "d715" = 4.25; taper "d716" = 0 deg
chamfer "Chamfer107" distance "d717" = 38.25; stored, may be unused: second distance "d718" = 22, angle "d719" = 45 deg
chamfer "Chamfer108" distance "d720" = 38.25; stored, may be unused: second distance "d721" = 20.25, angle "d722" = 45 deg
chamfer "Chamfer109" distance "d723" = 8; stored, may be unused: second distance "d724" = 20.25, angle "d725" = 45 deg
sketch "Sketch182"
  geometry: L1 (34, 4.183)-(78, 4.183) reference; L2 (34, -19)-(78, -19) reference; L3 (54, 4.183)-(54, -19); L4 (58, -19)-(58, 7); L5 (58, 7)-(54, 7); L6 (54, 7)-(54, 4.183); 1 further point
  constraints: 8 end point, 3 point on line, 2 parallel, 2 perpendicular
extrude "Extrusion182" join sketch "Sketch182" distance "d726" = 1; taper "d727" = 0 deg
sketch "Sketch183"
  geometry: L1 (-2, -7.408)-(113, -7.408); L2 (113, -7.408)-(113, -6); L3 (113, -6)-(-2, -6); L4 (-2, -6)-(-2, -7.408); L5 (113, -7.408)-(-2, -7.408); L6 (-2, -7.408)-(-2, -9); L7 (-2, -9)-(113, -9); L8 (113, -9)-(113, -7.408); 1 further point
  constraints: 16 end point, 4 parallel, 2 horizontal, 2 perpendicular
extrude "Extrusion183" join sketch "Sketch183" distance "d728" = 0.6; taper "d729" = 0 deg
chamfer "Chamfer110" distance "d730" = 0.6; stored, may be unused: second distance "d731" = 20.25, angle "d732" = 45 deg
chamfer "Chamfer111" distance "d733" = 1; stored, may be unused: second distance "d734" = 20.25, angle "d735" = 45 deg
chamfer "Chamfer112" distance "d736" = 2; stored, may be unused: second distance "d737" = 20.25, angle "d738" = 45 deg
sketch "Sketch184"
  geometry: L1 (-106.319, -22.522)-(-6.179, -22.522) reference; L2 (-82, -22.522)-(-28, -22.522); L3 (-28, -22.522)-(-28, -13); L4 (-28, -13)-(-82, -13); L5 (-82, -13)-(-82, -22.522); 1 further point
  constraints: 8 end point, 2 parallel, 1 horizontal, 1 perpendicular, 1 point on line
extrude "Extrusion184" join sketch "Sketch184" distance "d739" = 0.6; taper "d741" = 0 deg; dims "d740" = 2.8, "d742" = 0
chamfer "Chamfer113" distance "d743" = 2.5; stored, may be unused: second distance "d744" = 20.25, angle "d745" = 45 deg
chamfer "Chamfer114" distance "d746" = 0.5; stored, may be unused: second distance "d747" = 20.25, angle "d748" = 45 deg
chamfer "Chamfer115" distance "d749" = 0.5; stored, may be unused: second distance "d750" = 20.25, angle "d751" = 45 deg
chamfer "Chamfer116" distance "d752" = 0.5; stored, may be unused: second distance "d753" = 20.25, angle "d754" = 45 deg
body "Solid1"
